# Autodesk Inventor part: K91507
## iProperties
Author: Administrator
Shininess: 20.0
PropertySet Name: _Private Model Information
Created: 2001-03
Part Number: K91507
Document SubType Name: Modeling
Designer: Administrator
Description: Timken Tongued Washer, 1.396 in ID x 2.173 in
Control State: 0
Master: False
Checked Out: False
PropertySet Name: Design Tracking Control
Density: 0.0
Volumn: 0.0
Area: 0.0
PropertySet Name: Model Information
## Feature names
1. Extrusion1
